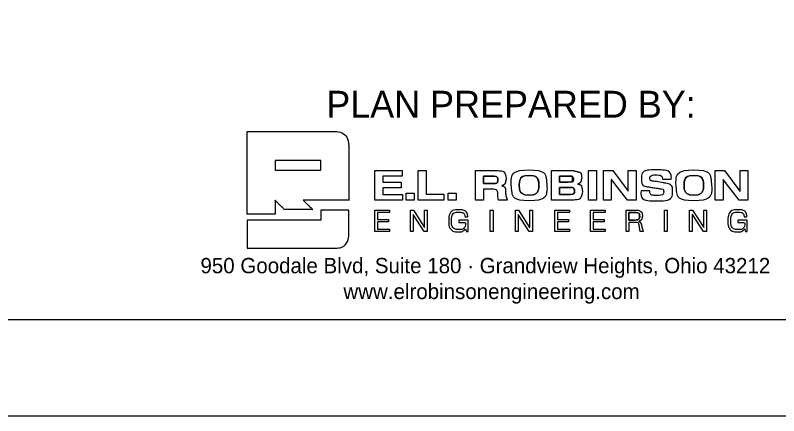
# Model space of a CAD drawing. Extents: x 0 to 34, y 0 to 22.
# Drawn here: x 1.992 to 5.97, y 0 to 2.086 of the extents above; entities that cross this region are included whole.
import ezdxf

# ---------------------------------------------------------------- set-up
doc = ezdxf.new("R2010")
doc.units = 0
for name, color, linetype in [('SH_Border', 7, 'Continuous'), ('SH_Cut_Line', 7, 'Continuous'), ('SH_Data', 7, 'Continuous'), ('SH_Text', 7, 'Continuous')]:
    doc.layers.add(name, color=color, linetype=linetype)

msp = doc.modelspace()

# ---------------------------------------------------------------- linework, layer by layer
at = {"layer": 'SH_Cut_Line'}
for p, q in [((3.584, 1.3306), (3.3461, 1.3306)), ((3.3461, 1.3306), (3.3461, 1.2789)), ((3.584, 1.2789), (3.584, 1.3306)), ((3.3461, 1.2789), (3.584, 1.2789)), ((4.4323, 1.2476), (4.4323, 1.2091)), ((4.8269, 1.2489), (4.8269, 1.216)), ((4.8269, 1.1894), (4.8269, 1.153)), ((5.1893, 1.0582), (5.1893, 1.0197)), ((5.1893, 1.0197), (5.2199, 1.0197))]:
    msp.add_line(p, q, dxfattribs=at)
for points in [[(3.8658, 1.2768), (4.0085, 1.2768), (4.0085, 1.2476), (3.9073, 1.2476), (3.9073, 1.216), (4.0034, 1.216), (4.0034, 1.1881), (3.9073, 1.1881), (3.9073, 1.153), (4.0094, 1.153), (4.0094, 1.1239), (3.8658, 1.1239), (3.8658, 1.2768)], [(4.0909, 1.2768), (4.1324, 1.2768), (4.1324, 1.1543), (4.2255, 1.1543), (4.2255, 1.1239), (4.0909, 1.1239), (4.0909, 1.2768)], [(4.9785, 1.2768), (5.02, 1.2768), (5.02, 1.1239), (4.9785, 1.1239), (4.9785, 1.2768)], [(5.1861, 1.2768), (5.2263, 1.2768), (5.2263, 1.1239), (5.1811, 1.1239), (5.0979, 1.2305), (5.0975, 1.2305), (5.0975, 1.1239), (5.0572, 1.1239), (5.0572, 1.2768), (5.1054, 1.2768), (5.1856, 1.1702), (5.1861, 1.1702), (5.1861, 1.2768)], [(5.7682, 1.2768), (5.8085, 1.2768), (5.8085, 1.1239), (5.7633, 1.1239), (5.68, 1.2305), (5.6796, 1.2305), (5.6796, 1.1239), (5.6394, 1.1239), (5.6394, 1.2768), (5.6875, 1.2768), (5.7678, 1.1702), (5.7682, 1.1702), (5.7682, 1.2768)], [(4.0281, 1.1603), (4.0697, 1.1603), (4.0697, 1.1239), (4.0281, 1.1239), (4.0281, 1.1603)], [(4.2473, 1.1603), (4.2889, 1.1603), (4.2889, 1.1239), (4.2473, 1.1239), (4.2473, 1.1603)], [(3.8654, 1.0705), (3.9415, 1.0705), (3.9415, 1.0582), (3.8801, 1.0582), (3.8801, 1.0231), (3.9373, 1.0231), (3.9373, 1.0108), (3.8801, 1.0108), (3.8801, 0.9726), (3.942, 0.9726), (3.942, 0.9603), (3.8654, 0.9603), (3.8654, 1.0705)], [(4.0511, 1.0705), (4.0667, 1.0705), (4.1248, 0.9811), (4.1251, 0.9811), (4.1251, 1.0705), (4.139, 1.0705), (4.139, 0.9603), (4.1229, 0.9603), (4.0653, 1.0487), (4.065, 1.0487), (4.065, 0.9603), (4.0511, 0.9603), (4.0511, 1.0705)], [(4.4669, 1.0705), (4.4816, 1.0705), (4.4816, 0.9603), (4.4669, 0.9603), (4.4669, 1.0705)], [(4.5984, 1.0705), (4.614, 1.0705), (4.6721, 0.9811), (4.6724, 0.9811), (4.6724, 1.0705), (4.6863, 1.0705), (4.6863, 0.9603), (4.6702, 0.9603), (4.6126, 1.0487), (4.6123, 1.0487), (4.6123, 0.9603), (4.5984, 0.9603), (4.5984, 1.0705)], [(4.8031, 1.0705), (4.8791, 1.0705), (4.8791, 1.0582), (4.8177, 1.0582), (4.8177, 1.0231), (4.875, 1.0231), (4.875, 1.0108), (4.8177, 1.0108), (4.8177, 0.9726), (4.8796, 0.9726), (4.8796, 0.9603), (4.8031, 0.9603), (4.8031, 1.0705)], [(4.9888, 1.0705), (5.0649, 1.0705), (5.0649, 1.0582), (5.0035, 1.0582), (5.0035, 1.0231), (5.0608, 1.0231), (5.0608, 1.0108), (5.0035, 1.0108), (5.0035, 0.9726), (5.0654, 0.9726), (5.0654, 0.9603), (4.9888, 0.9603), (4.9888, 1.0705)], [(5.3742, 1.0705), (5.3888, 1.0705), (5.3888, 0.9603), (5.3742, 0.9603), (5.3742, 1.0705)], [(5.5057, 1.0705), (5.5213, 1.0705), (5.5794, 0.9811), (5.5797, 0.9811), (5.5797, 1.0705), (5.5936, 1.0705), (5.5936, 0.9603), (5.5775, 0.9603), (5.5199, 1.0487), (5.5196, 1.0487), (5.5196, 0.9603), (5.5057, 0.9603), (5.5057, 1.0705)]]:
    msp.add_lwpolyline(points, dxfattribs=at)
for points, degree in [([(3.2003, 1.0494), (3.2003, 1.0515), (3.2003, 1.4789), (3.2003, 1.481)], 2), ([(3.2003, 1.481), (3.2025, 1.481), (3.6516, 1.481), (3.6538, 1.481), (3.6958, 1.481), (3.7297, 1.447), (3.7297, 1.4051)], 3), ([(3.7297, 1.4051), (3.7297, 1.4037), (3.7297, 1.1238), (3.7297, 1.1224)], 2), ([(4.3907, 1.1239), (4.3907, 1.1247), (4.3907, 1.276), (4.3907, 1.2768)], 2), ([(4.3907, 1.2768), (4.3913, 1.2768), (4.5013, 1.2768), (4.5018, 1.2768), (4.5442, 1.2768), (4.5487, 1.2504), (4.5499, 1.2351)], 3), ([(4.6692, 1.1196), (4.587, 1.1196), (4.5791, 1.1692), (4.5766, 1.2005), (4.5742, 1.2322), (4.587, 1.281), (4.6692, 1.281)], 3), ([(4.6692, 1.281), (4.7514, 1.281), (4.7593, 1.2314), (4.7617, 1.2001), (4.7642, 1.1684), (4.7514, 1.1196), (4.6692, 1.1196)], 3), ([(4.7854, 1.2768), (4.786, 1.2768), (4.8996, 1.2768), (4.9001, 1.2768)], 2), ([(4.7854, 1.1239), (4.7854, 1.1247), (4.7854, 1.276), (4.7854, 1.2768)], 2), ([(4.9001, 1.2768), (4.9212, 1.2717), (4.9432, 1.2665), (4.9432, 1.2382)], 2), ([(5.365, 1.2324), (5.3624, 1.2523), (5.3434, 1.2545), (5.3267, 1.2545), (5.3096, 1.2545), (5.2984, 1.2468), (5.2984, 1.2365), (5.2984, 1.2284), (5.3053, 1.2239), (5.316, 1.2222), (5.316, 1.2222), (5.368, 1.2138), (5.368, 1.2138), (5.3958, 1.2093), (5.417, 1.1988), (5.417, 1.171), (5.417, 1.1425), (5.3977, 1.1196), (5.3376, 1.1196), (5.3004, 1.1196), (5.252, 1.1243), (5.2516, 1.1721), (5.2516, 1.1721), (5.2982, 1.1721), (5.2982, 1.1721), (5.2986, 1.1511), (5.3196, 1.1475), (5.3376, 1.1475), (5.3571, 1.1475), (5.3704, 1.1532), (5.3704, 1.1665), (5.3704, 1.1783), (5.3609, 1.1815), (5.3445, 1.1841), (5.3445, 1.1841), (5.3066, 1.1898), (5.3066, 1.1898), (5.28, 1.1939), (5.2543, 1.2018), (5.2543, 1.2331), (5.2543, 1.2671), (5.2822, 1.281), (5.3301, 1.281), (5.3616, 1.281), (5.4082, 1.2757), (5.411, 1.2324), (5.411, 1.2324), (5.365, 1.2324), (5.365, 1.2324)], 3), ([(5.5274, 1.1196), (5.4453, 1.1196), (5.4374, 1.1692), (5.4349, 1.2005), (5.4324, 1.2322), (5.4453, 1.281), (5.5274, 1.281)], 3), ([(5.5274, 1.281), (5.6096, 1.281), (5.6175, 1.2314), (5.62, 1.2001), (5.6225, 1.1684), (5.6096, 1.1196), (5.5274, 1.1196)], 3), ([(4.4323, 1.2091), (4.4323, 1.2091), (4.4873, 1.2091), (4.4873, 1.2091), (4.4965, 1.2091), (4.5072, 1.2143), (4.5072, 1.2286), (4.5072, 1.2438), (4.4952, 1.2476), (4.4851, 1.2476), (4.4851, 1.2476), (4.4323, 1.2476), (4.4323, 1.2476), (4.4323, 1.2476), (4.4323, 1.2091), (4.4323, 1.2091)], 3), ([(4.4323, 1.2091), (4.4506, 1.2091), (4.4689, 1.2091), (4.4965, 1.2091), (4.5072, 1.2143), (4.5072, 1.2438), (4.4952, 1.2476), (4.4675, 1.2476), (4.4499, 1.2476), (4.4323, 1.2476)], 3), ([(4.5499, 1.2351), (4.5464, 1.2176), (4.5438, 1.2046), (4.5264, 1.1984)], 2), ([(4.6692, 1.1488), (4.7069, 1.1488), (4.7201, 1.1766), (4.7201, 1.2003), (4.7201, 1.2241), (4.7069, 1.2519), (4.6692, 1.2519), (4.6315, 1.2519), (4.6182, 1.2241), (4.6182, 1.2003), (4.6182, 1.1766), (4.6315, 1.1488), (4.6692, 1.1488)], 3), ([(4.6692, 1.2519), (4.6315, 1.2519), (4.6182, 1.2241), (4.6182, 1.2003), (4.6182, 1.1766), (4.6315, 1.1488), (4.6692, 1.1488)], 3), ([(4.6692, 1.1488), (4.7069, 1.1488), (4.7201, 1.1766), (4.7201, 1.2003), (4.7201, 1.2241), (4.7069, 1.2519), (4.6692, 1.2519)], 3), ([(4.8269, 1.216), (4.8269, 1.216), (4.8847, 1.216), (4.8847, 1.216), (4.8944, 1.216), (4.9003, 1.2211), (4.9003, 1.2324), (4.9003, 1.2421), (4.8961, 1.2489), (4.8789, 1.2489), (4.8789, 1.2489), (4.8269, 1.2489), (4.8269, 1.2489), (4.8269, 1.2489), (4.8269, 1.216), (4.8269, 1.216)], 3), ([(4.8269, 1.216), (4.8462, 1.216), (4.8655, 1.216), (4.8937, 1.2201), (4.8946, 1.2228), (4.8957, 1.2423), (4.8961, 1.2489), (4.8616, 1.2489), (4.8443, 1.2489), (4.8269, 1.2489)], 3), ([(4.9432, 1.2382), (4.9406, 1.227), (4.9372, 1.2121), (4.9228, 1.2076)], 2), ([(5.5274, 1.1488), (5.5651, 1.1488), (5.5784, 1.1766), (5.5784, 1.2003), (5.5784, 1.2241), (5.5651, 1.2519), (5.5274, 1.2519), (5.4898, 1.2519), (5.4765, 1.2241), (5.4765, 1.2003), (5.4765, 1.1766), (5.4898, 1.1488), (5.5274, 1.1488)], 3), ([(5.5274, 1.2519), (5.4898, 1.2519), (5.4765, 1.2241), (5.4765, 1.2003), (5.4765, 1.1766), (5.4898, 1.1488), (5.5274, 1.1488)], 3), ([(5.5274, 1.1488), (5.5651, 1.1488), (5.5784, 1.1766), (5.5784, 1.2003), (5.5784, 1.2241), (5.5651, 1.2519), (5.5274, 1.2519)], 3), ([(4.5264, 1.1984), (4.5264, 1.1984), (4.5264, 1.198), (4.5264, 1.198)], 2), ([(4.5264, 1.198), (4.5446, 1.1952), (4.5463, 1.172), (4.5471, 1.1571)], 2), ([(4.9228, 1.2076), (4.9228, 1.2076), (4.9228, 1.2072), (4.9228, 1.2072)], 2), ([(4.9228, 1.2072), (4.9406, 1.2042), (4.9445, 1.1852), (4.9476, 1.1699)], 2), ([(4.4838, 1.18), (4.4836, 1.18), (4.4325, 1.18), (4.4323, 1.18)], 2), ([(4.4323, 1.18), (4.4323, 1.1797), (4.4323, 1.1242), (4.4323, 1.1239)], 2), ([(4.51, 1.1239), (4.5076, 1.1315), (4.5072, 1.1373), (4.5066, 1.1533), (4.5059, 1.1747), (4.496, 1.1771), (4.4838, 1.18)], 3), ([(4.5471, 1.1571), (4.5473, 1.1496), (4.5525, 1.133), (4.5553, 1.1239)], 2), ([(4.9476, 1.1699), (4.9447, 1.1506), (4.9406, 1.1239), (4.8944, 1.1239), (4.8938, 1.1239), (4.7859, 1.1239), (4.7854, 1.1239)], 3), ([(4.8269, 1.153), (4.8269, 1.153), (4.8881, 1.153), (4.8881, 1.153), (4.901, 1.153), (4.9059, 1.1614), (4.9059, 1.171), (4.9059, 1.183), (4.8984, 1.1894), (4.8839, 1.1894), (4.8839, 1.1894), (4.8269, 1.1894), (4.8269, 1.1894), (4.8269, 1.1894), (4.8269, 1.153), (4.8269, 1.153)], 3), ([(4.8269, 1.153), (4.8473, 1.153), (4.8677, 1.153), (4.901, 1.153), (4.9059, 1.1614), (4.9059, 1.183), (4.8984, 1.1894), (4.8649, 1.1894), (4.8459, 1.1894), (4.8269, 1.1894)], 3), ([(3.3937, 1.0748), (3.3935, 1.075), (3.3463, 1.1222), (3.3461, 1.1224)], 2), ([(3.3461, 1.1224), (3.3461, 1.122), (3.3461, 1.0498), (3.3461, 1.0494)], 2), ([(3.7297, 1.1224), (3.7286, 1.1224), (3.4938, 1.1224), (3.4926, 1.1224)], 2), ([(3.4926, 1.1224), (3.4929, 1.1222), (3.5414, 1.075), (3.5417, 1.0748)], 2), ([(4.4323, 1.1239), (4.4321, 1.1239), (4.3909, 1.1239), (4.3907, 1.1239)], 2), ([(4.5553, 1.1239), (4.5551, 1.1239), (4.5102, 1.1239), (4.51, 1.1239)], 2), ([(3.5417, 1.0748), (3.5409, 1.0748), (3.3944, 1.0748), (3.3937, 1.0748)], 2), ([(3.3461, 1.0494), (3.3453, 1.0494), (3.201, 1.0494), (3.2003, 1.0494)], 2), ([(3.584, 1.0708), (3.584, 1.0708), (3.7297, 1.0708), (3.7297, 1.0708), (3.7297, 1.0708), (3.7297, 0.9491), (3.7297, 0.9491), (3.7297, 0.9072), (3.6958, 0.8732), (3.6538, 0.8732), (3.6538, 0.8732), (3.2003, 0.8732), (3.2003, 0.8732), (3.2003, 0.8732), (3.2003, 1.0191), (3.2003, 1.0191), (3.2003, 1.0191), (3.584, 1.0191), (3.584, 1.0191), (3.584, 1.0191), (3.584, 1.0708), (3.584, 1.0708)], 3), ([(4.3381, 0.974), (4.3296, 0.9625), (4.3157, 0.9577), (4.3027, 0.9577), (4.2699, 0.9577), (4.2503, 0.9845), (4.2503, 1.0132), (4.2503, 1.0453), (4.2679, 1.0731), (4.3027, 1.0731), (4.3268, 1.0731), (4.346, 1.0623), (4.3501, 1.0366), (4.3501, 1.0366), (4.3355, 1.0366), (4.3355, 1.0366), (4.3325, 1.0532), (4.3191, 1.0608), (4.3027, 1.0608), (4.276, 1.0608), (4.2649, 1.0376), (4.2649, 1.014), (4.2649, 0.991), (4.2782, 0.97), (4.3027, 0.97), (4.3254, 0.97), (4.339, 0.9859), (4.3381, 1.006), (4.3381, 1.006), (4.3029, 1.006), (4.3029, 1.006), (4.3029, 1.006), (4.3029, 1.0183), (4.3029, 1.0183), (4.3029, 1.0183), (4.3512, 1.0183), (4.3512, 1.0183), (4.3512, 1.0183), (4.3512, 0.9603), (4.3512, 0.9603), (4.3512, 0.9603), (4.342, 0.9603), (4.342, 0.9603), (4.342, 0.9603), (4.3381, 0.974), (4.3381, 0.974)], 3), ([(5.1746, 0.9603), (5.1746, 0.9608), (5.1746, 1.07), (5.1746, 1.0705)], 2), ([(5.1746, 1.0705), (5.1749, 1.0705), (5.2262, 1.0705), (5.2265, 1.0705), (5.2472, 1.0705), (5.26, 1.0592), (5.26, 1.0416)], 3), ([(5.2199, 1.0197), (5.2336, 1.0197), (5.2453, 1.0233), (5.2453, 1.0393), (5.2453, 1.0501), (5.2395, 1.0582), (5.2257, 1.0582), (5.2257, 1.0582), (5.1893, 1.0582), (5.1893, 1.0582), (5.1893, 1.0582), (5.1893, 1.0197), (5.1893, 1.0197), (5.1893, 1.0197), (5.2199, 1.0197), (5.2199, 1.0197)], 3), ([(5.2199, 1.0197), (5.2336, 1.0197), (5.2453, 1.0233), (5.2453, 1.0501), (5.2395, 1.0582), (5.2136, 1.0582), (5.2014, 1.0582), (5.1893, 1.0582)], 3), ([(5.26, 1.0416), (5.257, 1.0291), (5.2541, 1.0174), (5.2409, 1.0137)], 2), ([(5.7927, 0.974), (5.7842, 0.9625), (5.7703, 0.9577), (5.7573, 0.9577), (5.7245, 0.9577), (5.7049, 0.9845), (5.7049, 1.0132), (5.7049, 1.0453), (5.7224, 1.0731), (5.7573, 1.0731), (5.7814, 1.0731), (5.8005, 1.0623), (5.8047, 1.0366), (5.8047, 1.0366), (5.7901, 1.0366), (5.7901, 1.0366), (5.7871, 1.0532), (5.7737, 1.0608), (5.7573, 1.0608), (5.7306, 1.0608), (5.7195, 1.0376), (5.7195, 1.014), (5.7195, 0.991), (5.7328, 0.97), (5.7573, 0.97), (5.78, 0.97), (5.7936, 0.9859), (5.7927, 1.006), (5.7927, 1.006), (5.7575, 1.006), (5.7575, 1.006), (5.7575, 1.006), (5.7575, 1.0183), (5.7575, 1.0183), (5.7575, 1.0183), (5.8058, 1.0183), (5.8058, 1.0183), (5.8058, 1.0183), (5.8058, 0.9603), (5.8058, 0.9603), (5.8058, 0.9603), (5.7965, 0.9603), (5.7965, 0.9603), (5.7965, 0.9603), (5.7927, 0.974), (5.7927, 0.974)], 3), ([(5.1893, 1.0074), (5.1893, 1.0071), (5.1893, 0.9605), (5.1893, 0.9603)], 2), ([(5.2435, 0.9875), (5.2413, 0.9981), (5.2393, 1.0074), (5.2251, 1.0074), (5.2249, 1.0074), (5.1895, 1.0074), (5.1893, 1.0074)], 3), ([(5.2409, 1.0137), (5.2409, 1.0137), (5.2409, 1.0134), (5.2409, 1.0134)], 2), ([(5.2409, 1.0134), (5.2501, 1.0063), (5.253, 1), (5.2556, 0.9902)], 2), ([(5.1893, 0.9603), (5.1892, 0.9603), (5.1747, 0.9603), (5.1746, 0.9603)], 2), ([(5.2475, 0.9603), (5.2469, 0.9652), (5.2452, 0.9766), (5.2435, 0.9875)], 2), ([(5.2639, 0.9603), (5.2638, 0.9603), (5.2476, 0.9603), (5.2475, 0.9603)], 2), ([(5.2556, 0.9902), (5.2566, 0.9797), (5.2606, 0.969), (5.2639, 0.9603)], 2)]:
    msp.add_open_spline(points, degree=degree, dxfattribs=at)
at = {"layer": 'SH_Data'}
msp.add_lwpolyline([(1.5, 21.5), (33.5, 21.5), (33.5, 0.5), (1.5, 0.5)], close=True, dxfattribs=at)
at = {"layer": 'SH_Text'}
msp.add_lwpolyline([(0, 0), (34, 0), (34, 22), (0, 22)], close=True, dxfattribs=at)

# ---------------------------------------------------------------- texts
at = {"layer": 'SH_Border'}
msp.add_text('PLAN PREPARED BY:', height=0.14, dxfattribs=at).set_placement((3.6125, 1.553))
at = {"layer": 'SH_Cut_Line'}
for s, p in [('950 Goodale Blvd, Suite 180 · Grandview Heights, Ohio 43212', (2.9572, 0.7422)), ('www.elrobinsonengineering.com', (3.7019, 0.6077))]:
    msp.add_text(s, height=0.079861, dxfattribs=at).set_placement(p)

doc.saveas('drawing.dxf')
